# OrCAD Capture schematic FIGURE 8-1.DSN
size A
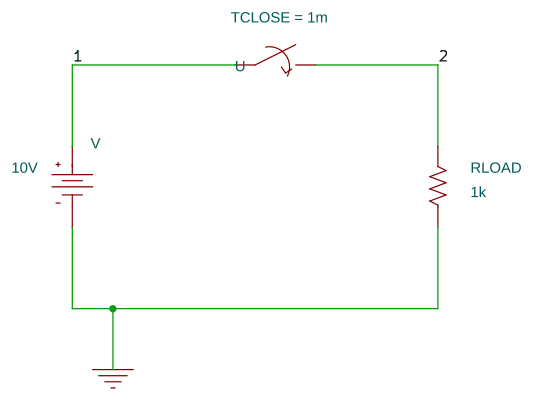
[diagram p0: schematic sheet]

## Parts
RLOAD  1k  [AX/RC05]
U  Sw_tClose
V  VDC

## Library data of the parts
RLOAD = R
U = Sw_tClose: TCLOSE: 1m
V = VDC: DC: 10V

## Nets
0: RLOAD.1 V.1(-)
1: U.1 V.0(+)
2: RLOAD.2 U.2
